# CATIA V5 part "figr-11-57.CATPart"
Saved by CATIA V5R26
Part number: Part1
Bounding box of the stored display mesh (mm): x -55 to 55, y -105 to 155, z -20 to 14.953
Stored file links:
  D:\_Deepak\CATIA\CATIA V5-6R2016_Deepak\Resources\Part files\Partfiles\c11_catia_v5_6r2016_prt\figr-11-57.CATPart
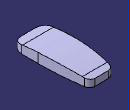
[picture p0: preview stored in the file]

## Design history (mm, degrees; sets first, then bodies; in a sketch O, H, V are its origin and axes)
Set1
  Extrude1: Element1 Sketch2, Lim1 50, Lim2 50, Direction yz-plane
  Sketch1 on xy-plane, origin (0, 0, 0), H (1, 0, 0), V (0, 1, 0)
    arc A1 centre (25, -75) radius 25 from (25, -100) to (50, -75) ccw
    line L1 (50, -75) -> (50, -15)
    point P4 (50, -15)
    arc A2 centre (-950, -15) radius 1000 from (50, -15) to (38.3367, 137.2843) ccw
    line L2 (23.5117, 150) -> (-23.5117, 150)
    line L3 (25, -100) -> (-25, -100)
    arc A3 centre (-25, -75) radius 25 from (-25, -100) to (-50, -75) cw
    line L4 (-50, -75) -> (-50, -15)
    point P9 (-50, -15)
    arc A4 centre (950, -15) radius 1000 from (-50, -15) to (-38.3367, 137.2843) cw
    reference projected line E1 (-50, -100) -> (50, -100) from edge of Extrude1
    axis line L5 (0, 170.4214) -> (0, -120.6595)
    point P11 (0, 170.4214)
    reference projected line E2 (50, -70) -> (50, 129.9971) from edge of Extrude1
    reference projected line E3 (-50, 129.9971) -> (-50, -70) from edge of Extrude1
    reference projected line E4 (-50, -100) -> (50, -100) from edge of Extrude1
    reference projected line E5 (50, 150) -> (-50, 150) from edge of Extrude1
    arc A5 centre (-23.5117, 135) radius 15 from (-38.3367, 137.2843) to (-23.5117, 150) cw
    arc A6 centre (23.5117, 135) radius 15 from (38.3367, 137.2843) to (23.5117, 150) ccw
    distance E4 P4 = 85
    radius A2 = 1000
    radius A5 = 15
    radius A6 = 15
    radius A1 = 25
    radius A3 = 25
    radius A4 = 1000
    tangency: L1 A1, A2 L1, L3 A1, A3 L3, A4 L4, L5 A3, A5 L2, A5 A4, A6 A2, A6 L2, A3 L4
    horizontal: L2 H
    coincidence: L3 E1, P11 V, L1 E2, L4 E3, L2 E5
    symmetry: P4 P9 L5
  Extrude2: Element1 Sketch1, Lim1 50, Lim2 20, Direction xy-plane
  Split1: ToCut Extrude2, Cutting Extrude1
  Split2: ToCut Extrude1, Cutting Split1
  Join1: Elements (Split2; Split1)
Body1 (main body)
  Sketch2 on yz-plane, origin (0, 0, 0), H (0, 1, 0), V (0, 0, 1)
    point P1 (-100, 0)
    line L1 (-100, 0) -> (-70, 3.8724)
    point P2 (-70, 3.8724)
    arc A1 centre (26.0141, -739.9564) radius 750 from (-70, 3.8724) to (129.9971, 2.8003) cw
    point P4 (129.9971, 2.8003)
    line L2 (129.9971, 2.8003) -> (150, 0)
    point P5 (150, 0)
    distance P1 P5 = 250
    distance P1 O = 100
    radius A1 = 750
    distance P2 P4 = 200
    distance P2 V = 70
    coincidence: P1 H, P5 H
    tangency: A1 L1, L2 A1
  ThickSurface1: BotOffset 0, Surface Join1, TopOffset 5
